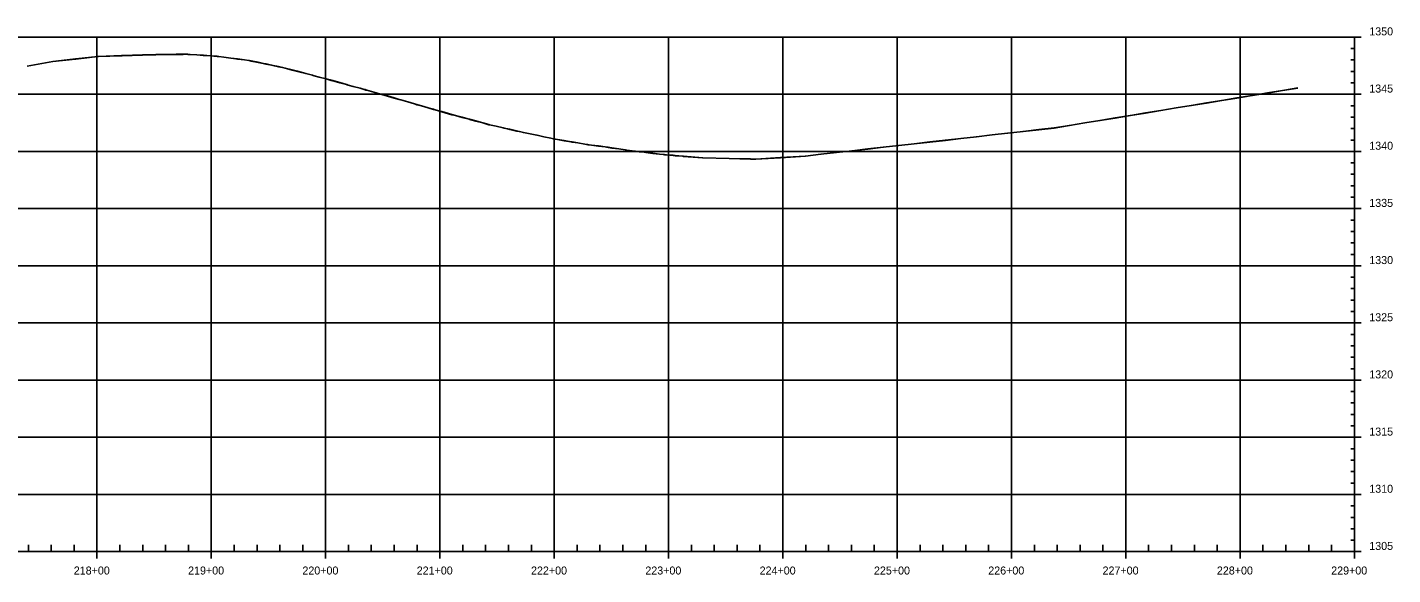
# Model space of a CAD drawing. Extents: x 1371206 to 1374178, y 379328 to 381511.
# Drawn here: x 1372984 to 1374178, y 379328 to 379807 of the extents above; entities that cross this region are included whole.
import ezdxf

# ---------------------------------------------------------------- set-up
doc = ezdxf.new("R2010")
doc.units = 0
for name, color, linetype in [('30', 7, 'Continuous'), ('37', 7, 'Continuous'), ('R_Exist Surface', 7, 'Continuous')]:
    doc.layers.add(name, color=color, linetype=linetype)

msp = doc.modelspace()

# ---------------------------------------------------------------- linework, layer by layer
at = {"layer": '37'}
for p, q in [((1371244.6, 379798.4), (1374144.6, 379798.4)), ((1371244.6, 379798.4), (1374144.6, 379798.4)), ((1373044.6, 379348.4), (1373044.6, 379798.4)), ((1373144.6, 379348.4), (1373144.6, 379798.4)), ((1373244.6, 379348.4), (1373244.6, 379798.4)), ((1373344.6, 379348.4), (1373344.6, 379798.4)), ((1373444.6, 379348.4), (1373444.6, 379798.4)), ((1373544.6, 379348.4), (1373544.6, 379798.4)), ((1373644.6, 379348.4), (1373644.6, 379798.4)), ((1373744.6, 379348.4), (1373744.6, 379798.4)), ((1373844.6, 379348.4), (1373844.6, 379798.4)), ((1373944.6, 379348.4), (1373944.6, 379798.4)), ((1374044.6, 379348.4), (1374044.6, 379798.4)), ((1374144.6, 379348.4), (1374144.6, 379798.4)), ((1374150.6, 379798.4), (1374144.6, 379798.4)), ((1374150.6, 379798.4), (1374144.6, 379798.4)), ((1374144.6, 379788.4), (1374141.6, 379788.4)), ((1374144.6, 379778.4), (1374141.6, 379778.4)), ((1374144.6, 379768.4), (1374141.6, 379768.4)), ((1374144.6, 379758.4), (1374141.6, 379758.4)), ((1371244.6, 379748.4), (1374144.6, 379748.4)), ((1374144.6, 379738.4), (1374141.6, 379738.4)), ((1374150.6, 379748.4), (1374144.6, 379748.4)), ((1374144.6, 379728.4), (1374141.6, 379728.4)), ((1374144.6, 379718.4), (1374141.6, 379718.4)), ((1374144.6, 379708.4), (1374141.6, 379708.4)), ((1371244.6, 379698.4), (1374144.6, 379698.4)), ((1374150.6, 379698.4), (1374144.6, 379698.4)), ((1374144.6, 379688.4), (1374141.6, 379688.4)), ((1374144.6, 379678.4), (1374141.6, 379678.4)), ((1374144.6, 379668.4), (1374141.6, 379668.4)), ((1374144.6, 379658.4), (1374141.6, 379658.4)), ((1371244.6, 379648.4), (1374144.6, 379648.4)), ((1374150.6, 379648.4), (1374144.6, 379648.4)), ((1374144.6, 379638.4), (1374141.6, 379638.4)), ((1374144.6, 379628.4), (1374141.6, 379628.4)), ((1374144.6, 379618.4), (1374141.6, 379618.4)), ((1374144.6, 379608.4), (1374141.6, 379608.4)), ((1371244.6, 379598.4), (1374144.6, 379598.4)), ((1374150.6, 379598.4), (1374144.6, 379598.4)), ((1374144.6, 379588.4), (1374141.6, 379588.4)), ((1374144.6, 379578.4), (1374141.6, 379578.4)), ((1374144.6, 379568.4), (1374141.6, 379568.4)), ((1374144.6, 379558.4), (1374141.6, 379558.4)), ((1371244.6, 379548.4), (1374144.6, 379548.4)), ((1374150.6, 379548.4), (1374144.6, 379548.4)), ((1374144.6, 379538.4), (1374141.6, 379538.4)), ((1374144.6, 379528.4), (1374141.6, 379528.4)), ((1374144.6, 379518.4), (1374141.6, 379518.4)), ((1371244.6, 379498.4), (1374144.6, 379498.4)), ((1374144.6, 379508.4), (1374141.6, 379508.4)), ((1374150.6, 379498.4), (1374144.6, 379498.4)), ((1374144.6, 379488.4), (1374141.6, 379488.4)), ((1374144.6, 379478.4), (1374141.6, 379478.4)), ((1374144.6, 379468.4), (1374141.6, 379468.4)), ((1374144.6, 379458.4), (1374141.6, 379458.4)), ((1371244.6, 379448.4), (1374144.6, 379448.4)), ((1374144.6, 379438.4), (1374141.6, 379438.4)), ((1374150.6, 379448.4), (1374144.6, 379448.4)), ((1374144.6, 379428.4), (1374141.6, 379428.4)), ((1374144.6, 379418.4), (1374141.6, 379418.4)), ((1374144.6, 379408.4), (1374141.6, 379408.4)), ((1371244.6, 379398.4), (1374144.6, 379398.4)), ((1374150.6, 379398.4), (1374144.6, 379398.4)), ((1374144.6, 379388.4), (1374141.6, 379388.4)), ((1374144.6, 379378.4), (1374141.6, 379378.4)), ((1374144.6, 379368.4), (1374141.6, 379368.4)), ((1374144.6, 379358.4), (1374141.6, 379358.4)), ((1371244.6, 379348.4), (1374144.6, 379348.4)), ((1372984.6, 379348.4), (1372984.6, 379354.4)), ((1373004.6, 379348.4), (1373004.6, 379354.4)), ((1373024.6, 379348.4), (1373024.6, 379354.4)), ((1373044.6, 379342.4), (1373044.6, 379348.4)), ((1373064.6, 379348.4), (1373064.6, 379354.4)), ((1373084.6, 379348.4), (1373084.6, 379354.4)), ((1373104.6, 379348.4), (1373104.6, 379354.4)), ((1373124.6, 379348.4), (1373124.6, 379354.4)), ((1373144.6, 379342.4), (1373144.6, 379348.4)), ((1373164.6, 379348.4), (1373164.6, 379354.4)), ((1373184.6, 379348.4), (1373184.6, 379354.4)), ((1373204.6, 379348.4), (1373204.6, 379354.4)), ((1373224.6, 379348.4), (1373224.6, 379354.4)), ((1373244.6, 379342.4), (1373244.6, 379348.4)), ((1373264.6, 379348.4), (1373264.6, 379354.4)), ((1373284.6, 379348.4), (1373284.6, 379354.4)), ((1373304.6, 379348.4), (1373304.6, 379354.4)), ((1373324.6, 379348.4), (1373324.6, 379354.4)), ((1373344.6, 379342.4), (1373344.6, 379348.4)), ((1373364.6, 379348.4), (1373364.6, 379354.4)), ((1373384.6, 379348.4), (1373384.6, 379354.4)), ((1373404.6, 379348.4), (1373404.6, 379354.4)), ((1373424.6, 379348.4), (1373424.6, 379354.4)), ((1373444.6, 379342.4), (1373444.6, 379348.4)), ((1373464.6, 379348.4), (1373464.6, 379354.4)), ((1373484.6, 379348.4), (1373484.6, 379354.4)), ((1373504.6, 379348.4), (1373504.6, 379354.4)), ((1373524.6, 379348.4), (1373524.6, 379354.4)), ((1373544.6, 379342.4), (1373544.6, 379348.4)), ((1373564.6, 379348.4), (1373564.6, 379354.4)), ((1373584.6, 379348.4), (1373584.6, 379354.4)), ((1373604.6, 379348.4), (1373604.6, 379354.4)), ((1373624.6, 379348.4), (1373624.6, 379354.4)), ((1373644.6, 379342.4), (1373644.6, 379348.4)), ((1373664.6, 379348.4), (1373664.6, 379354.4)), ((1373684.6, 379348.4), (1373684.6, 379354.4)), ((1373704.6, 379348.4), (1373704.6, 379354.4)), ((1373724.6, 379348.4), (1373724.6, 379354.4)), ((1373744.6, 379342.4), (1373744.6, 379348.4)), ((1373764.6, 379348.4), (1373764.6, 379354.4)), ((1373784.6, 379348.4), (1373784.6, 379354.4)), ((1373804.6, 379348.4), (1373804.6, 379354.4)), ((1373824.6, 379348.4), (1373824.6, 379354.4)), ((1373844.6, 379342.4), (1373844.6, 379348.4)), ((1373864.6, 379348.4), (1373864.6, 379354.4)), ((1373884.6, 379348.4), (1373884.6, 379354.4)), ((1373904.6, 379348.4), (1373904.6, 379354.4)), ((1373924.6, 379348.4), (1373924.6, 379354.4)), ((1373944.6, 379342.4), (1373944.6, 379348.4)), ((1373964.6, 379348.4), (1373964.6, 379354.4)), ((1373984.6, 379348.4), (1373984.6, 379354.4)), ((1374004.6, 379348.4), (1374004.6, 379354.4)), ((1374024.6, 379348.4), (1374024.6, 379354.4)), ((1374044.6, 379342.4), (1374044.6, 379348.4)), ((1374064.6, 379348.4), (1374064.6, 379354.4)), ((1374084.6, 379348.4), (1374084.6, 379354.4)), ((1374104.6, 379348.4), (1374104.6, 379354.4)), ((1374124.6, 379348.4), (1374124.6, 379354.4)), ((1374150.6, 379348.4), (1374144.6, 379348.4)), ((1374144.6, 379342.4), (1374144.6, 379348.4))]:
    msp.add_line(p, q, dxfattribs=at)
at = {"layer": 'R_Exist Surface'}
for points in [[(1372983.6, 379773.1), (1373006.1, 379777.2), (1373025.7, 379779.3), (1373026, 379779.3), (1373045.4, 379781.4), (1373045.8, 379781.4), (1373066.1, 379782.2), (1373066.5, 379782.2), (1373084.3, 379782.9), (1373086.7, 379783), (1373087.2, 379783), (1373090.2, 379783), (1373096.2, 379783.1), (1373102.1, 379783.2), (1373105.5, 379783.3), (1373105.6, 379783.3), (1373105.7, 379783.3), (1373108.1, 379783.3), (1373114, 379783.4), (1373120, 379783.4), (1373123.9, 379783.5), (1373124.2, 379783.5), (1373126, 379783.3), (1373131.9, 379782.9), (1373137.6, 379782.5), (1373137.8, 379782.5), (1373137.9, 379782.5), (1373143.8, 379782), (1373149.8, 379781.6), (1373151.3, 379781.4), (1373155.7, 379780.9), (1373161.7, 379780.1), (1373164.1, 379779.8), (1373164.3, 379779.8), (1373164.6, 379779.7), (1373167.6, 379779.3), (1373173.6, 379778.5), (1373177.3, 379778), (1373177.8, 379777.9), (1373179.5, 379777.5), (1373185.5, 379776.4), (1373191.4, 379775.1), (1373192.1, 379775), (1373192.6, 379774.9), (1373197.4, 379773.9), (1373203.4, 379772.6), (1373206.9, 379771.9), (1373209.3, 379771.3), (1373215.3, 379769.7), (1373220.1, 379768.5), (1373220.8, 379768.3), (1373221.2, 379768.2), (1373227.2, 379766.7), (1373233.1, 379765.1), (1373233.7, 379764.9), (1373234.7, 379764.6), (1373239.1, 379763.5), (1373245, 379761.9), (1373248.6, 379761), (1373249.6, 379760.7), (1373251, 379760.3), (1373256.9, 379758.6), (1373262.9, 379757), (1373263.3, 379756.9), (1373264.4, 379756.5), (1373268.8, 379755.3), (1373274.8, 379753.7), (1373278.2, 379752.7), (1373279.1, 379752.5), (1373279.9, 379752.2), (1373280.7, 379752), (1373286.7, 379750.3), (1373292.7, 379748.6), (1373293.7, 379748.2), (1373294.6, 379748), (1373298.6, 379746.9), (1373304.6, 379745.2), (1373309, 379743.9), (1373310.5, 379743.5), (1373316.5, 379741.8), (1373322.4, 379740), (1373323.3, 379739.7), (1373324.3, 379739.4), (1373328.4, 379738.3), (1373334.3, 379736.6), (1373338.9, 379735.4), (1373339.6, 379735.1), (1373340.3, 379734.9), (1373340.3, 379734.9), (1373346.2, 379733.2), (1373352.2, 379731.5), (1373354.9, 379730.6), (1373358.1, 379729.8), (1373364.1, 379728.3), (1373370.1, 379726.7), (1373370.7, 379726.5), (1373371.2, 379726.4), (1373371.7, 379726.3), (1373376, 379725.1), (1373382, 379723.5), (1373387.5, 379721.9), (1373387.9, 379721.8), (1373393.9, 379720.5), (1373399.8, 379719.1), (1373400.7, 379718.9), (1373400.8, 379718.9), (1373403.8, 379718.2), (1373405.8, 379717.8), (1373411.7, 379716.4), (1373414, 379715.8), (1373414.1, 379715.8), (1373417.7, 379715.1), (1373423.6, 379713.8), (1373429.4, 379712.6), (1373429.6, 379712.6), (1373435.5, 379711.3), (1373441.5, 379710), (1373444, 379709.4), (1373444.7, 379709.3), (1373445.4, 379709.1), (1373447.4, 379708.8), (1373453.4, 379707.9), (1373459.3, 379706.9), (1373459.4, 379706.9), (1373460.4, 379706.7), (1373465.3, 379705.9), (1373471.3, 379704.9), (1373474, 379704.4), (1373475.3, 379704.2), (1373477.2, 379704), (1373483.2, 379703.2), (1373489.1, 379702.4), (1373490.3, 379702.2), (1373491.9, 379702), (1373495.1, 379701.5), (1373501, 379700.7), (1373506.6, 379699.9), (1373507, 379699.8), (1373508.2, 379699.6), (1373512.9, 379699), (1373518.9, 379698.4), (1373523.2, 379697.9), (1373524.8, 379697.5), (1373524.8, 379697.5), (1373530.8, 379696.8), (1373536.7, 379696.1), (1373539.9, 379695.8), (1373541.1, 379695.6), (1373542.7, 379695.5), (1373548.7, 379695), (1373550.4, 379694.8), (1373557.1, 379694.3), (1373557.8, 379694.2), (1373574.3, 379692.8), (1373574.6, 379692.8), (1373597.6, 379692.2), (1373597.7, 379692.2), (1373616.2, 379691.8), (1373620.9, 379691.6), (1373620.9, 379691.6), (1373642.6, 379693), (1373642.6, 379693), (1373664.3, 379694.4), (1373664.3, 379694.4), (1373677.9, 379696), (1373677.9, 379696), (1373691.5, 379697.5), (1373691.6, 379697.5), (1373705.2, 379699), (1373705.2, 379699), (1373718.8, 379700.6), (1373718.8, 379700.6), (1373732.4, 379702.1), (1373732.4, 379702.1), (1373746, 379703.7), (1373746, 379703.7), (1373759.6, 379705.2), (1373759.6, 379705.2), (1373773.2, 379706.7), (1373773.2, 379706.7), (1373786.8, 379708.3), (1373786.8, 379708.3), (1373800.4, 379709.8), (1373814, 379711.3), (1373814, 379711.3), (1373827.6, 379712.9), (1373827.6, 379712.9), (1373841.2, 379714.4), (1373841.2, 379714.4), (1373854.8, 379715.9), (1373854.8, 379715.9), (1373868.4, 379717.5), (1373868.4, 379717.5), (1373882, 379719), (1373882, 379719), (1373895.3, 379721.2), (1373895.3, 379721.2), (1373908.7, 379723.4), (1373908.7, 379723.4), (1373922, 379725.6), (1373922, 379725.6), (1373935.3, 379727.7), (1373935.3, 379727.7), (1373948.6, 379729.9), (1373948.6, 379729.9), (1373961.9, 379732.1), (1373961.9, 379732.1), (1373975.2, 379734.3), (1373975.3, 379734.3), (1373988.6, 379736.5), (1373988.6, 379736.5), (1374001.9, 379738.7), (1374001.9, 379738.7), (1374015.2, 379740.8), (1374015.2, 379740.8), (1374028.5, 379743), (1374028.5, 379743), (1374041.8, 379745.2), (1374041.8, 379745.2), (1374055.2, 379747.4), (1374055.2, 379747.4), (1374068.5, 379749.6), (1374068.5, 379749.6), (1374081.8, 379751.7), (1374095.1, 379753.9)], [(1372983.6, 379773), (1373006.1, 379777.1), (1373025.7, 379779.2), (1373026, 379779.2), (1373045.4, 379781.3), (1373045.8, 379781.3), (1373066.1, 379782.1), (1373066.5, 379782.1), (1373084.3, 379782.7), (1373086.7, 379782.8), (1373087.2, 379782.8), (1373090.2, 379782.9), (1373096.2, 379783), (1373102.1, 379783.1), (1373105.5, 379783.2), (1373105.6, 379783.1), (1373105.7, 379783.1), (1373108.1, 379783.2), (1373114, 379783.3), (1373120, 379783.3), (1373123.9, 379783.4), (1373124.2, 379783.3), (1373126, 379783.2), (1373131.9, 379782.8), (1373137.6, 379782.4), (1373137.8, 379782.4), (1373137.9, 379782.4), (1373143.8, 379781.9), (1373149.8, 379781.5), (1373151.3, 379781.3), (1373155.7, 379780.8), (1373161.7, 379780), (1373164.1, 379779.7), (1373164.3, 379779.6), (1373164.6, 379779.6), (1373167.6, 379779.2), (1373173.6, 379778.4), (1373177.3, 379777.9), (1373177.8, 379777.8), (1373179.5, 379777.4), (1373185.5, 379776.2), (1373191.4, 379775), (1373192.1, 379774.9), (1373192.6, 379774.8), (1373197.4, 379773.8), (1373203.4, 379772.5), (1373206.9, 379771.7), (1373209.3, 379771.1), (1373215.3, 379769.6), (1373220.1, 379768.4), (1373220.8, 379768.2), (1373221.2, 379768.1), (1373227.2, 379766.5), (1373233.1, 379765), (1373233.7, 379764.8), (1373234.7, 379764.5), (1373239.1, 379763.4), (1373245, 379761.8), (1373248.6, 379760.8), (1373249.6, 379760.5), (1373251, 379760.2), (1373256.9, 379758.5), (1373262.9, 379756.9), (1373263.3, 379756.7), (1373264.4, 379756.4), (1373268.8, 379755.2), (1373274.8, 379753.6), (1373278.2, 379752.6), (1373279.1, 379752.4), (1373279.9, 379752.1), (1373280.7, 379751.9), (1373286.7, 379750.2), (1373292.7, 379748.4), (1373293.7, 379748.1), (1373294.6, 379747.9), (1373298.6, 379746.8), (1373304.6, 379745.1), (1373309, 379743.8), (1373310.5, 379743.4), (1373316.5, 379741.7), (1373322.4, 379739.9), (1373323.3, 379739.6), (1373324.3, 379739.3), (1373328.4, 379738.2), (1373334.3, 379736.5), (1373338.9, 379735.2), (1373339.6, 379735), (1373340.3, 379734.8), (1373340.3, 379734.8), (1373346.2, 379733.1), (1373352.2, 379731.3), (1373354.9, 379730.5), (1373358.1, 379729.7), (1373364.1, 379728.2), (1373370.1, 379726.6), (1373370.7, 379726.4), (1373371.2, 379726.3), (1373371.7, 379726.1), (1373376, 379725), (1373382, 379723.3), (1373387.5, 379721.8), (1373387.9, 379721.7), (1373393.9, 379720.4), (1373399.8, 379719), (1373400.7, 379718.8), (1373400.8, 379718.8), (1373403.8, 379718.1), (1373405.8, 379717.7), (1373411.7, 379716.2), (1373414, 379715.7), (1373414.1, 379715.7), (1373417.7, 379714.9), (1373423.6, 379713.7), (1373429.4, 379712.5), (1373429.6, 379712.5), (1373435.5, 379711.2), (1373441.5, 379709.9), (1373444, 379709.3), (1373444.7, 379709.1), (1373445.4, 379709), (1373447.4, 379708.7), (1373453.4, 379707.8), (1373459.3, 379706.8), (1373459.4, 379706.8), (1373460.4, 379706.6), (1373465.3, 379705.8), (1373471.3, 379704.8), (1373474, 379704.3), (1373475.3, 379704.1), (1373477.2, 379703.9), (1373483.2, 379703.1), (1373489.1, 379702.3), (1373490.3, 379702.1), (1373491.9, 379701.8), (1373495.1, 379701.4), (1373501, 379700.6), (1373506.6, 379699.8), (1373507, 379699.7), (1373508.2, 379699.5), (1373512.9, 379698.9), (1373518.9, 379698.2), (1373523.2, 379697.7), (1373524.8, 379697.4), (1373524.8, 379697.4), (1373530.8, 379696.7), (1373536.7, 379696), (1373539.9, 379695.6), (1373541.1, 379695.5), (1373542.7, 379695.4), (1373548.7, 379694.9), (1373550.4, 379694.7), (1373557.1, 379694.2), (1373557.8, 379694.1), (1373574.3, 379692.7), (1373574.6, 379692.7), (1373597.6, 379692.1), (1373597.7, 379692.1), (1373616.2, 379691.7), (1373620.9, 379691.5), (1373620.9, 379691.5), (1373642.6, 379692.9), (1373642.6, 379692.9), (1373664.3, 379694.3), (1373664.3, 379694.3), (1373677.9, 379695.9), (1373677.9, 379695.9), (1373691.5, 379697.4), (1373691.6, 379697.4), (1373705.2, 379698.9), (1373705.2, 379698.9), (1373718.8, 379700.5), (1373718.8, 379700.5), (1373732.4, 379702), (1373732.4, 379702), (1373746, 379703.5), (1373746, 379703.5), (1373759.6, 379705.1), (1373759.6, 379705.1), (1373773.2, 379706.6), (1373773.2, 379706.6), (1373786.8, 379708.1), (1373786.8, 379708.1), (1373800.4, 379709.7), (1373814, 379711.2), (1373814, 379711.2), (1373827.6, 379712.8), (1373827.6, 379712.8), (1373841.2, 379714.3), (1373841.2, 379714.3), (1373854.8, 379715.8), (1373854.8, 379715.8), (1373868.4, 379717.4), (1373868.4, 379717.4), (1373882, 379718.9), (1373882, 379718.9), (1373895.3, 379721.1), (1373895.3, 379721.1), (1373908.7, 379723.3), (1373908.7, 379723.3), (1373922, 379725.4), (1373922, 379725.4), (1373935.3, 379727.6), (1373935.3, 379727.6), (1373948.6, 379729.8), (1373948.6, 379729.8), (1373961.9, 379732), (1373961.9, 379732), (1373975.2, 379734.2), (1373975.3, 379734.2), (1373988.6, 379736.4), (1373988.6, 379736.4), (1374001.9, 379738.5), (1374001.9, 379738.5), (1374015.2, 379740.7), (1374015.2, 379740.7), (1374028.5, 379742.9), (1374028.5, 379742.9), (1374041.8, 379745.1), (1374041.8, 379745.1), (1374055.2, 379747.3), (1374055.2, 379747.3), (1374068.5, 379749.4), (1374068.5, 379749.4), (1374081.8, 379751.6), (1374095.1, 379753.8)]]:
    msp.add_lwpolyline(points, dxfattribs=at)

# ---------------------------------------------------------------- texts
at = {"layer": '30'}
for s, p in [('1350', (1374157.6, 379799.9)), ('1350', (1374157.6, 379799.9)), ('1345', (1374157.6, 379749.9)), ('1340', (1374157.6, 379699.9)), ('1335', (1374157.6, 379649.9)), ('1330', (1374157.6, 379599.9)), ('1325', (1374157.6, 379549.9)), ('1320', (1374157.6, 379499.9)), ('1315', (1374157.6, 379449.9)), ('1310', (1374157.6, 379399.9)), ('1305', (1374157.6, 379349.9)), ('218+00', (1373024.3, 379328.4)), ('219+00', (1373124.3, 379328.4)), ('220+00', (1373224.3, 379328.4)), ('221+00', (1373324.3, 379328.4)), ('222+00', (1373424.3, 379328.4)), ('223+00', (1373524.3, 379328.4)), ('224+00', (1373624.3, 379328.4)), ('225+00', (1373724.3, 379328.4)), ('226+00', (1373824.3, 379328.4)), ('227+00', (1373924.3, 379328.4)), ('228+00', (1374024.3, 379328.4)), ('229+00', (1374124.3, 379328.4))]:
    msp.add_text(s, height=7, dxfattribs=at).set_placement(p)

doc.saveas('drawing.dxf')
